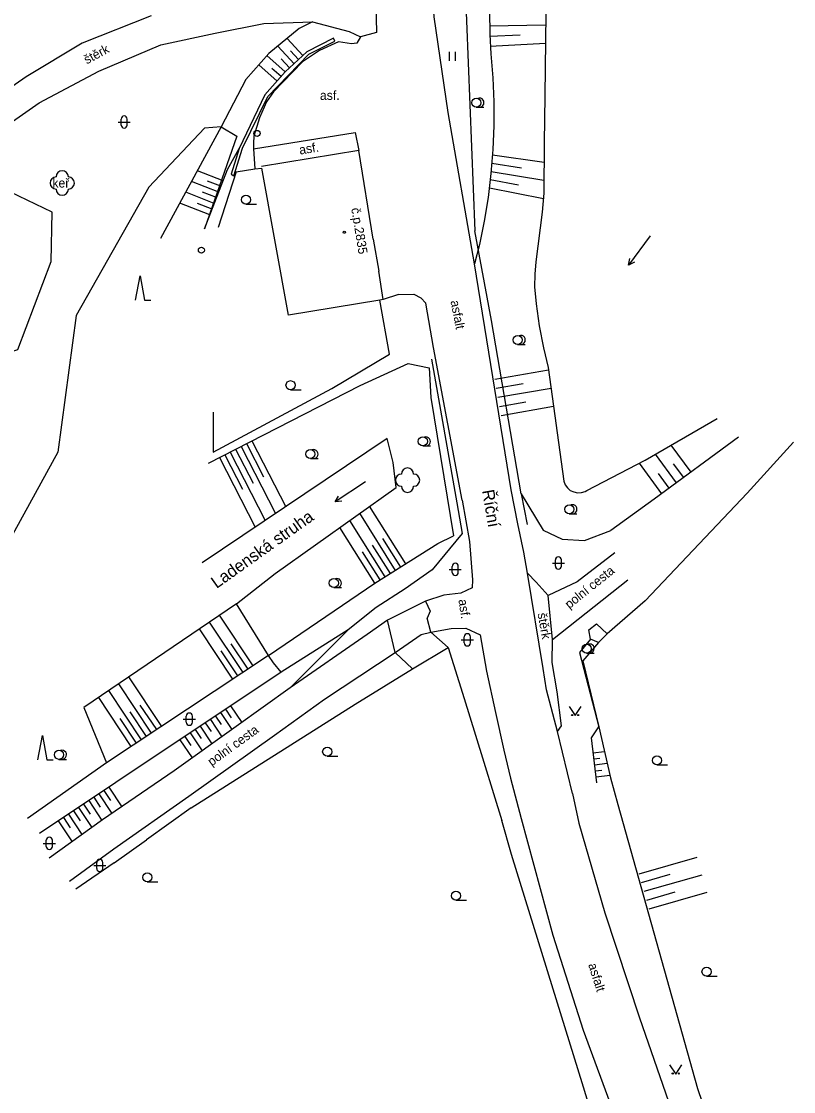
# Model space of a CAD drawing. Extents: x -584400 to -581602, y -1210894 to -1208793.
# Drawn here: x -583059.4 to -582996.1, y -1209395.2 to -1209307.4 of the extents above; entities that cross this region are included whole.
import ezdxf

# ---------------------------------------------------------------- set-up
doc = ezdxf.new("R2010")
doc.units = 0
for name, color, linetype in [('BUDOVY_MĚŘ', 7, 'Continuous'), ('BUDOVY_NEMĚŘ', 7, 'Continuous'), ('NÁZVY_ULIC_TOK_SMĚR', 7, 'Continuous'), ('POMOC_POPIS', 7, 'Continuous'), ('ROZHRANÍ_PLOCH', 7, 'Continuous'), ('VÝŠKOPIS', 7, 'Continuous'), ('ZELEŇ', 7, 'Continuous'), ('ZN_BUDOV', 7, 'Continuous'), ('ZN_DOPLŇKOVÉ', 7, 'Continuous'), ('ZN_KULTUR', 7, 'Continuous'), ('Č_POPIS_ORIENT', 7, 'Continuous')]:
    doc.layers.add(name, color=color, linetype=linetype)

msp = doc.modelspace()

# ---------------------------------------------------------------- linework, layer by layer
at = {"layer": 'BUDOVY_MĚŘ'}
for points in [[(-583030.53, -1209325.27), (-583031.73, -1209318), (-583039.7, -1209319.32)], [(-583029.71, -1209330.22), (-583030.09, -1209327.9)], [(-583029.71, -1209330.22), (-583030, -1209330.27)]]:
    msp.add_lwpolyline(points, dxfattribs=at)
at = {"layer": 'BUDOVY_NEMĚŘ'}
msp.add_lwpolyline([(-583030, -1209330.27), (-583037.49, -1209331.52), (-583039.68, -1209319.45)], dxfattribs=at)
at = {"layer": 'ROZHRANÍ_PLOCH'}
for points in [[(-583024.38, -1209314.88), (-583025.54, -1209307.04), (-583025.97, -1209300.74), (-583026.02, -1209293.23), (-583025.39, -1209285), (-583023.4, -1209274.85), (-583020.65, -1209265.06)], [(-583030.65, -1209293.31), (-583030.43, -1209301.16), (-583030.27, -1209308.32), (-583031.59, -1209308.69)], [(-583048.76, -1209306.95), (-583054.41, -1209309.21), (-583059, -1209311.95), (-583067.75, -1209318.04), (-583077.03, -1209324.86), (-583091.54, -1209334.49), (-583099.69, -1209339.61), (-583098.4, -1209342.8), (-583089.37, -1209336.23), (-583075.72, -1209326.79), (-583066.02, -1209319.73), (-583057.94, -1209314.1), (-583053.04, -1209311.48), (-583047.95, -1209309.34), (-583043.5, -1209308.38), (-583039.51, -1209307.57), (-583035.53, -1209307.45)], [(-583035.53, -1209307.45), (-583032.52, -1209308.24), (-583031.59, -1209308.69)], [(-583031.59, -1209308.69), (-583031.87, -1209309.2), (-583032.31, -1209309.26), (-583033.38, -1209309.08), (-583034.94, -1209309.8), (-583036.35, -1209310.74), (-583038.73, -1209313.19), (-583039.28, -1209314.01), (-583039.88, -1209315.31), (-583040.32, -1209316.82), (-583040.37, -1209317.41), (-583040.35, -1209317.86)], [(-583022.22, -1209327.31), (-583024.38, -1209314.88)], [(-583040.35, -1209317.86), (-583032.01, -1209316.52), (-583031.73, -1209318)], [(-583040.35, -1209317.86), (-583040.24, -1209319.5)], [(-583019.21, -1209345.84), (-583022.22, -1209327.31)], [(-583028.45, -1209329.81), (-583029.71, -1209330.22)], [(-583028.45, -1209329.81), (-583027.2, -1209329.79), (-583026.63, -1209330.08), (-583026.21, -1209330.53)], [(-583025.6, -1209334.16), (-583026.21, -1209330.53)], [(-583023.24, -1209346.69), (-583025.6, -1209334.16)], [(-583014.18, -1209370.76), (-583015.42, -1209365.68), (-583016.33, -1209362.26), (-583016.59, -1209360.5), (-583017.89, -1209352.67), (-583018.19, -1209350.96), (-583018.66, -1209348.63), (-583019.21, -1209345.84)], [(-583023.24, -1209346.69), (-583022.65, -1209350.08), (-583022.39, -1209353.24), (-583022.41, -1209353.88), (-583023.36, -1209354.31), (-583024.75, -1209354.49), (-583026.26, -1209354.99), (-583025.86, -1209355.79), (-583026.12, -1209356.37)], [(-583010.71, -1209351.01), (-583013.81, -1209353.39), (-583016.19, -1209354.51)], [(-583015.42, -1209365.68), (-583015.09, -1209365.2), (-583015.44, -1209362.42), (-583015.87, -1209360), (-583015.83, -1209358.13), (-583016.19, -1209354.51), (-583017.17, -1209353.41), (-583017.89, -1209352.67)], [(-583015.83, -1209358.13), (-583009.66, -1209353.23)], [(-583026.26, -1209354.99), (-583029.37, -1209356.55), (-583031.03, -1209357.71), (-583037.34, -1209362.09), (-583041.77, -1209365.26), (-583046.87, -1209368.89), (-583052.74, -1209372.93), (-583057.12, -1209376.05)], [(-583041.76, -1209355.2), (-583054.27, -1209363.7)], [(-583025.81, -1209357.51), (-583026.12, -1209356.37)], [(-583055.45, -1209377.94), (-583051.81, -1209375.29), (-583045.67, -1209370.97), (-583038.65, -1209365.97), (-583034.54, -1209363.03), (-583028.73, -1209359.18), (-583026.61, -1209357.7), (-583025.81, -1209357.51)], [(-583025.81, -1209357.51), (-583024.13, -1209357.21), (-583022.93, -1209357.18), (-583021.77, -1209357.73), (-583021.25, -1209360.71), (-583020.5, -1209364.12), (-583019.83, -1209367.21), (-583019.28, -1209369.49), (-583018.4, -1209372.8)], [(-583014.18, -1209370.76), (-583013.67, -1209373.19), (-583011.53, -1209380.55), (-583008.69, -1209389.17), (-583006.31, -1209396.03), (-583004.85, -1209400.01), (-583002.36, -1209406.52), (-583001.22, -1209409.38)], [(-583018.4, -1209372.8), (-583015.79, -1209382.38), (-583013.32, -1209390.18), (-583010.75, -1209397.15), (-583007.61, -1209405.53)]]:
    msp.add_lwpolyline(points, dxfattribs=at)
at = {"layer": 'VÝŠKOPIS'}
for points in [[(-583014.89, -1209294.71), (-583015.74, -1209299.14), (-583016.05, -1209301.82), (-583016.37, -1209306.75), (-583016.47, -1209313.52), (-583016.51, -1209317.37), (-583016.55, -1209321.51), (-583016.68, -1209323.06), (-583017.21, -1209327.13)], [(-583020.65, -1209304.48), (-583021.01, -1209306.53), (-583020.98, -1209308.49), (-583020.89, -1209310.07), (-583020.73, -1209312.03), (-583020.65, -1209314), (-583020.65, -1209315.97), (-583020.72, -1209317.93), (-583020.88, -1209319.89), (-583021.12, -1209321.85), (-583021.44, -1209323.79), (-583021.83, -1209325.71), (-583022.22, -1209327.31)], [(-583035.53, -1209307.45), (-583036.6, -1209307.99), (-583039.11, -1209310.04), (-583040.99, -1209312.18), (-583043, -1209316.05)], [(-583016.39, -1209307.72), (-583020.99, -1209307.81)], [(-583036.3, -1209310.2), (-583037.59, -1209308.8)], [(-583018.47, -1209308.55), (-583020.97, -1209308.64)], [(-583016.41, -1209309.22), (-583020.93, -1209309.47)], [(-583037.03, -1209310.88), (-583038.37, -1209309.44)], [(-583036.66, -1209310.54), (-583037.32, -1209309.83)], [(-583038.43, -1209312.31), (-583039.93, -1209310.97)], [(-583037.76, -1209311.56), (-583039.27, -1209310.22)], [(-583037.4, -1209311.22), (-583038.08, -1209310.49)], [(-583038.09, -1209311.94), (-583038.85, -1209311.27)], [(-583043, -1209316.05), (-583047.98, -1209325.21)], [(-583044.39, -1209324.43), (-583042.49, -1209319.55), (-583041.53, -1209317.84)], [(-583016.52, -1209318.98), (-583020.75, -1209318.39)], [(-583042.85, -1209320.48), (-583044.96, -1209319.66)], [(-583016.53, -1209320.47), (-583020.86, -1209319.75)], [(-583018.37, -1209319.44), (-583020.8, -1209319.07)], [(-583043.21, -1209321.41), (-583045.44, -1209320.54)], [(-583043.03, -1209320.94), (-583044.12, -1209320.52)], [(-583018.61, -1209320.85), (-583020.93, -1209320.42)], [(-583043.58, -1209322.34), (-583045.92, -1209321.43)], [(-583043.4, -1209321.87), (-583044.54, -1209321.43)], [(-583016.58, -1209321.97), (-583021.01, -1209321.1)], [(-583043.94, -1209323.27), (-583046.4, -1209322.31)], [(-583043.76, -1209322.81), (-583044.96, -1209322.34)], [(-583017.21, -1209327.13), (-583017.29, -1209328.16), (-583017.3, -1209329.2), (-583017.18, -1209330.59), (-583016.91, -1209332.39), (-583016.57, -1209334.18), (-583016.18, -1209335.82)], [(-583044.05, -1209343.65), (-583031.62, -1209337.27), (-583027.66, -1209335.47), (-583025.96, -1209335.84), (-583025.81, -1209338.27), (-583023.95, -1209349.63)], [(-583016.15, -1209336.03), (-583020.57, -1209336.8)], [(-583016.18, -1209335.82), (-583014.9, -1209345.13)], [(-583018.24, -1209337.16), (-583020.44, -1209337.54)], [(-583015.94, -1209337.52), (-583020.31, -1209338.28)], [(-583018.01, -1209338.64), (-583020.18, -1209339.02)], [(-583015.74, -1209339), (-583020.05, -1209339.76)], [(-583013.01, -1209345.89), (-583008.22, -1209343.4), (-583002.31, -1209340)], [(-583038.57, -1209352.71), (-583028.65, -1209345.64), (-583028.89, -1209343.6), (-583029.39, -1209341.64), (-583044.56, -1209351.82)], [(-583000.57, -1209341.51), (-583007.48, -1209346.6), (-583011.04, -1209349.19)], [(-583041.83, -1209342.51), (-583040.4, -1209345.29)], [(-583041.38, -1209342.28), (-583038.55, -1209347.79)], [(-583040.94, -1209342.05), (-583039.54, -1209344.78)], [(-583040.49, -1209341.82), (-583037.72, -1209347.23)], [(-583006.11, -1209342.18), (-583004.48, -1209344.39)], [(-583043.16, -1209343.19), (-583040.23, -1209348.91)], [(-583042.72, -1209342.97), (-583041.26, -1209345.8)], [(-583042.27, -1209342.74), (-583039.39, -1209348.35)], [(-583007.41, -1209342.93), (-583005.68, -1209345.27)], [(-583008.72, -1209343.66), (-583006.88, -1209346.16)], [(-583005.92, -1209343.7), (-583005.08, -1209344.83)], [(-583014.9, -1209345.13), (-583014.79, -1209345.42), (-583014.61, -1209345.68), (-583014.37, -1209345.89), (-583014.08, -1209346.02), (-583013.78, -1209346.09), (-583013.46, -1209346.07), (-583013.16, -1209345.97), (-583013.01, -1209345.89)], [(-583007.17, -1209344.51), (-583006.28, -1209345.72)], [(-583028.71, -1209352.45), (-583031.64, -1209347.77)], [(-583027.86, -1209351.91), (-583030.83, -1209347.19)], [(-583029.55, -1209352.98), (-583032.46, -1209348.35)], [(-583030.4, -1209353.51), (-583033.27, -1209348.94)], [(-583039.14, -1209359.44), (-583030.4, -1209353.51), (-583025.23, -1209350.26), (-583023.95, -1209349.63)], [(-583029.13, -1209352.71), (-583030.59, -1209350.39)], [(-583028.28, -1209352.18), (-583029.76, -1209349.83)], [(-583029.98, -1209353.24), (-583031.42, -1209350.94)], [(-583041.76, -1209355.2), (-583038.57, -1209352.71)], [(-583040.39, -1209360.27), (-583043.14, -1209356.13)], [(-583028.73, -1209359.18), (-583029.37, -1209356.55)], [(-583042.06, -1209361.38), (-583044.79, -1209357.26)], [(-583041.22, -1209360.82), (-583043.96, -1209356.7)], [(-583032.58, -1209357.33), (-583037.34, -1209362.09)], [(-583025.81, -1209357.51), (-583024.39, -1209358.79)], [(-583012.7, -1209358.09), (-583012.84, -1209357.32), (-583012.23, -1209356.85), (-583011.34, -1209357.65)], [(-583041.64, -1209361.1), (-583043.01, -1209359.04)], [(-583040.81, -1209360.55), (-583042.18, -1209358.48)], [(-583028.73, -1209359.18), (-583027.32, -1209360.53)], [(-583039.14, -1209359.44), (-583052.41, -1209368.25)], [(-583038.1, -1209360.8), (-583051.65, -1209369.86), (-583057.92, -1209374.03)], [(-583048.72, -1209365.8), (-583051.41, -1209361.75)], [(-583047.89, -1209365.25), (-583050.58, -1209361.19)], [(-583049.55, -1209366.35), (-583052.23, -1209362.32)], [(-583050.39, -1209366.91), (-583053.06, -1209362.88)], [(-583048.3, -1209365.52), (-583049.65, -1209363.5)], [(-583042.24, -1209363.57), (-583041.32, -1209364.94)], [(-583049.14, -1209366.08), (-583050.48, -1209364.06)], [(-583043.49, -1209364.4), (-583043.02, -1209365.11)], [(-583043.07, -1209364.12), (-583042.14, -1209365.52)], [(-583042.66, -1209363.85), (-583042.19, -1209364.54)], [(-583049.97, -1209366.63), (-583051.31, -1209364.61)], [(-583044.73, -1209365.24), (-583043.77, -1209366.68)], [(-583044.32, -1209364.96), (-583043.84, -1209365.67)], [(-583043.9, -1209364.68), (-583042.95, -1209366.1)], [(-583012.2, -1209369.89), (-583012.64, -1209366.18), (-583012.04, -1209365.3)], [(-583045.98, -1209366.07), (-583045.49, -1209366.81)], [(-583045.56, -1209365.79), (-583044.58, -1209367.26)], [(-583045.15, -1209365.51), (-583044.66, -1209366.24)], [(-583046.4, -1209366.35), (-583045.4, -1209367.84)], [(-583012.49, -1209367.41), (-583011.58, -1209367.3)], [(-583012.44, -1209367.9), (-583011.95, -1209367.85)], [(-583012.38, -1209368.4), (-583011.35, -1209368.28)], [(-583012.32, -1209368.9), (-583011.78, -1209368.83)], [(-583012.26, -1209369.39), (-583011.12, -1209369.26)], [(-583052.63, -1209370.51), (-583052.1, -1209371.32)], [(-583052.22, -1209370.24), (-583051.15, -1209371.84)], [(-583053.88, -1209371.34), (-583052.8, -1209372.97)], [(-583053.47, -1209371.07), (-583052.93, -1209371.88)], [(-583053.05, -1209370.79), (-583051.98, -1209372.4)], [(-583055.13, -1209372.17), (-583054.58, -1209373.01)], [(-583054.71, -1209371.9), (-583053.61, -1209373.55)], [(-583054.3, -1209371.62), (-583053.75, -1209372.44)], [(-583056.38, -1209373.01), (-583055.24, -1209374.71)], [(-583055.96, -1209372.73), (-583055.4, -1209373.58)], [(-583055.55, -1209372.45), (-583054.43, -1209374.13)], [(-583004, -1209376), (-583008.76, -1209377.37)], [(-583006.19, -1209377.41), (-583008.55, -1209378.09)], [(-583003.58, -1209377.45), (-583008.34, -1209378.81)], [(-583005.78, -1209378.86), (-583008.13, -1209379.53)], [(-583003.17, -1209378.89), (-583007.92, -1209380.25)]]:
    msp.add_lwpolyline(points, dxfattribs=at)
at = {"layer": 'ZELEŇ'}
for points in [[(-583023.02, -1209303.89), (-583022.2, -1209324.58)], [(-583043, -1209316.05), (-583044.38, -1209316.16), (-583048.94, -1209321.01), (-583054.92, -1209331.55), (-583056.41, -1209342.75), (-583061.85, -1209352.63), (-583069.22, -1209360.34), (-583096.19, -1209376.59), (-583130.78, -1209402.41), (-583140.19, -1209404.77), (-583148.02, -1209386.1), (-583155.04, -1209381.85)], [(-583043, -1209316.05), (-583041.72, -1209316.84), (-583044.39, -1209324.43)], [(-583060.3, -1209321.43), (-583063.49, -1209323.85), (-583066.72, -1209328.07), (-583063.31, -1209335.53), (-583059.69, -1209334.33), (-583056.96, -1209327.11), (-583056.89, -1209323.07), (-583060.3, -1209321.43)], [(-583018.39, -1209346.18), (-583016.6, -1209349.16), (-583015.03, -1209349.89), (-583013.21, -1209350.01), (-583011.04, -1209349.19)], [(-583023.25, -1209349.42), (-583025.71, -1209352.42), (-583027.91, -1209353.96), (-583030.29, -1209355.49), (-583032.58, -1209357.33), (-583038.1, -1209360.8), (-583038.73, -1209360.05), (-583039.14, -1209359.44), (-583041.76, -1209355.2)], [(-583054.27, -1209363.7), (-583052.41, -1209368.25), (-583058.9, -1209372.81)]]:
    msp.add_lwpolyline(points, dxfattribs=at)
for centre in [(-583056.05, -1209320.67), (-583027.72, -1209345.05)]:
    msp.add_circle(centre, 0.0005, dxfattribs=at)
for centre, start, end in [((-583056.05, -1209320.17), 0, 179.99999), ((-583056.55, -1209320.67), 89.99999, 269.99999), ((-583055.55, -1209320.67), 270, 89.99999), ((-583056.05, -1209321.17), 179.99999, 359.99999), ((-583027.72, -1209344.55), 0, 179.99999), ((-583028.22, -1209345.05), 89.99999, 269.99999), ((-583027.22, -1209345.05), 270, 89.99999), ((-583027.72, -1209345.55), 179.99999, 359.99999)]:
    msp.add_arc(centre, 0.5, start, end, dxfattribs=at)
at = {"layer": 'ZN_BUDOV'}
msp.add_circle((-583032.91, -1209324.71), 0.0875, dxfattribs=at)
at = {"layer": 'ZN_DOPLŇKOVÉ'}
for points in [[(-583041.53, -1209317.84), (-583042.19, -1209319.95), (-583041.96, -1209320.07), (-583041.27, -1209317.82), (-583039.19, -1209313.57), (-583035.83, -1209310.09), (-583033.68, -1209309.03), (-583033.79, -1209308.79), (-583035.99, -1209309.92), (-583037.76, -1209311.56), (-583039.43, -1209313.44), (-583041.53, -1209317.84)], [(-583041.79, -1209319.75), (-583043.25, -1209324.33)], [(-583041.79, -1209319.75), (-583040.24, -1209319.5)], [(-583040.24, -1209319.5), (-583039.68, -1209319.45)], [(-583018.39, -1209346.18), (-583020.83, -1209331.94), (-583022.2, -1209324.58)], [(-583030.53, -1209325.27), (-583030.09, -1209327.9)], [(-583029.19, -1209334.71), (-583030, -1209330.27)], [(-583033.93, -1209337.54), (-583029.19, -1209334.71)], [(-583025.75, -1209335.12), (-583023.68, -1209346.91)], [(-583043.68, -1209342.76), (-583033.93, -1209337.54)], [(-583043.68, -1209339.47), (-583043.68, -1209342.76)], [(-582999.86, -1209346.13), (-582996.05, -1209341.92)], [(-583023.68, -1209346.91), (-583023.25, -1209349.42)], [(-583018.39, -1209346.18), (-583017.92, -1209348.69)], [(-582999.86, -1209346.13), (-583008.22, -1209354.95)], [(-583008.22, -1209354.95), (-583011.34, -1209357.65)], [(-583012.06, -1209358.38), (-583012.7, -1209358.09), (-583013.62, -1209359.2), (-583012.04, -1209365.3)], [(-583012.06, -1209358.38), (-583013.34, -1209359.86), (-583012.04, -1209365.3), (-583011.07, -1209369.46), (-583010.46, -1209371.65)], [(-583012.06, -1209358.38), (-583011.34, -1209357.65)], [(-583045.47, -1209371.92), (-583032.01, -1209363.43), (-583027.32, -1209360.53), (-583024.39, -1209358.79), (-583023.07, -1209362.97)], [(-583023.07, -1209362.97), (-583022.14, -1209365.97)], [(-583022.14, -1209365.97), (-583019.98, -1209372.98)], [(-583045.47, -1209371.92), (-583049.14, -1209374.56)], [(-583010.46, -1209371.65), (-583003.94, -1209394.97)], [(-583013.29, -1209394.86), (-583019.18, -1209375.75), (-583019.98, -1209372.98)], [(-583051.79, -1209376.45), (-583049.14, -1209374.56)], [(-583051.79, -1209376.45), (-583054.93, -1209378.61)], [(-583012.91, -1209396.1), (-583013.29, -1209394.86)], [(-583003.94, -1209394.97), (-583002.84, -1209398.16)]]:
    msp.add_lwpolyline(points, dxfattribs=at)
for centre, radius in [((-583040.07, -1209316.6), 0.25), ((-583040.07, -1209316.6), 0.0005), ((-583044.63, -1209326.18), 0.25), ((-583044.63, -1209326.18), 0.0005)]:
    msp.add_circle(centre, radius, dxfattribs=at)
at = {"layer": 'ZN_KULTUR'}
for p, q in [((-583024.28, -1209310.645), (-583024.28, -1209309.895)), ((-583023.78, -1209310.645), (-583023.78, -1209309.895)), ((-583022.08, -1209314.455), (-583021.455, -1209314.455)), ((-583051.47, -1209315.67), (-583050.47, -1209315.67)), ((-583051.22, -1209315.92), (-583051.22, -1209315.42)), ((-583050.72, -1209315.92), (-583050.72, -1209315.42)), ((-583040.98, -1209322.415), (-583040.105, -1209322.415)), ((-583007.813, -1209325), (-583009.587, -1209327.42)), ((-583018.69, -1209333.925), (-583018.065, -1209333.925)), ((-583037.32, -1209337.635), (-583036.445, -1209337.635)), ((-583026.47, -1209342.245), (-583025.845, -1209342.245)), ((-583035.69, -1209343.285), (-583035.065, -1209343.285)), ((-583031.169, -1209345.183), (-583033.671, -1209346.837)), ((-583014.45, -1209347.815), (-583013.825, -1209347.815)), ((-583024.06, -1209352.62), (-583024.06, -1209352.12)), ((-583023.56, -1209352.62), (-583023.56, -1209352.12)), ((-583015.84, -1209351.85), (-583014.84, -1209351.85)), ((-583015.59, -1209352.1), (-583015.59, -1209351.6)), ((-583015.09, -1209352.1), (-583015.09, -1209351.6)), ((-583024.31, -1209352.37), (-583023.31, -1209352.37)), ((-583033.77, -1209353.865), (-583033.145, -1209353.865)), ((-583023.32, -1209358.15), (-583022.32, -1209358.15)), ((-583023.07, -1209358.4), (-583023.07, -1209357.9)), ((-583022.57, -1209358.4), (-583022.57, -1209357.9)), ((-583013.03, -1209359.245), (-583012.405, -1209359.245)), ((-583045.87, -1209364.91), (-583045.87, -1209364.41)), ((-583045.37, -1209364.91), (-583045.37, -1209364.41)), ((-583046.12, -1209364.66), (-583045.12, -1209364.66)), ((-583056.32, -1209367.955), (-583055.695, -1209367.955)), ((-583034.31, -1209367.705), (-583033.435, -1209367.705)), ((-583007.26, -1209368.415), (-583006.385, -1209368.415)), ((-583057.61, -1209374.85), (-583056.61, -1209374.85)), ((-583057.36, -1209375.1), (-583057.36, -1209374.6)), ((-583056.86, -1209375.1), (-583056.86, -1209374.6)), ((-583053.47, -1209376.66), (-583052.47, -1209376.66)), ((-583053.22, -1209376.91), (-583053.22, -1209376.41)), ((-583052.72, -1209376.91), (-583052.72, -1209376.41)), ((-583049.07, -1209378.015), (-583048.195, -1209378.015)), ((-583023.75, -1209379.515), (-583022.875, -1209379.515)), ((-583003.19, -1209385.755), (-583002.315, -1209385.755))]:
    msp.add_line(p, q, dxfattribs=at)
for points in [[(-583009.089, -1209327.164), (-583009.587, -1209327.42), (-583009.493, -1209326.869)], [(-583050.045, -1209330.29), (-583049.67, -1209328.29), (-583049.295, -1209330.29), (-583048.795, -1209330.29)], [(-583033.117, -1209346.77), (-583033.671, -1209346.837), (-583033.392, -1209346.353)], [(-583014.47, -1209363.62), (-583013.97, -1209364.37), (-583013.47, -1209363.62)], [(-583058.055, -1209367.99), (-583057.68, -1209365.99), (-583057.305, -1209367.99), (-583056.805, -1209367.99)], [(-583006.22, -1209393.03), (-583005.72, -1209393.78), (-583005.22, -1209393.03)]]:
    msp.add_lwpolyline(points, dxfattribs=at)
for centre, radius in [((-583022.08, -1209314.08), 0.375), ((-583040.98, -1209322.04), 0.375), ((-583018.69, -1209333.55), 0.375), ((-583037.32, -1209337.26), 0.375), ((-583026.47, -1209341.87), 0.375), ((-583035.69, -1209342.91), 0.375), ((-583014.45, -1209347.44), 0.375), ((-583033.77, -1209353.49), 0.375), ((-583013.03, -1209358.87), 0.375), ((-583014.22, -1209364.32), 0.05), ((-583013.72, -1209364.32), 0.05), ((-583034.31, -1209367.33), 0.375), ((-583056.32, -1209367.58), 0.375), ((-583007.26, -1209368.04), 0.375), ((-583049.07, -1209377.64), 0.375), ((-583023.75, -1209379.14), 0.375), ((-583003.19, -1209385.38), 0.375), ((-583005.97, -1209393.73), 0.05), ((-583005.47, -1209393.73), 0.05)]:
    msp.add_circle(centre, radius, dxfattribs=at)
for centre, radius, start, end in [((-583021.83, -1209314.08), 0.375, 249.49437, 109.04743), ((-583050.97, -1209315.42), 0.25, 0, 179.99999), ((-583050.97, -1209315.92), 0.25, 179.99999, 359.99999), ((-583018.44, -1209333.55), 0.375, 249.49437, 109.04743), ((-583026.22, -1209341.87), 0.375, 249.49437, 109.04743), ((-583035.44, -1209342.91), 0.375, 249.49437, 109.04743), ((-583014.2, -1209347.44), 0.375, 249.49437, 109.04743), ((-583015.34, -1209351.6), 0.25, 0, 179.99999), ((-583023.81, -1209352.12), 0.25, 0, 179.99999), ((-583015.34, -1209352.1), 0.25, 179.99999, 359.99999), ((-583033.52, -1209353.49), 0.375, 249.49437, 109.04743), ((-583023.81, -1209352.62), 0.25, 179.99999, 359.99999), ((-583022.82, -1209357.9), 0.25, 0, 179.99999), ((-583022.82, -1209358.4), 0.25, 179.99999, 359.99999), ((-583012.78, -1209358.87), 0.375, 249.49437, 109.04743), ((-583045.62, -1209364.41), 0.25, 0, 179.99999), ((-583045.62, -1209364.91), 0.25, 179.99999, 359.99999), ((-583056.07, -1209367.58), 0.375, 249.49437, 109.04743), ((-583057.11, -1209374.6), 0.25, 0, 179.99999), ((-583057.11, -1209375.1), 0.25, 179.99999, 359.99999), ((-583052.97, -1209376.41), 0.25, 0, 179.99999), ((-583052.97, -1209376.91), 0.25, 179.99999, 359.99999)]:
    msp.add_arc(centre, radius, start, end, dxfattribs=at)

# ---------------------------------------------------------------- texts
at = {"layer": 'NÁZVY_ULIC_TOK_SMĚR'}
for s, rotation, p in [('Říční', 279.90856, (-583021.62, -1209345.91)), ('Ladenská struha', 35.33637, (-583043.39, -1209353.98))]:
    msp.add_text(s, height=1, rotation=rotation, dxfattribs=at).set_placement(p)
at = {"layer": 'POMOC_POPIS'}
for s, rotation, p in [('štěrk', 28.13314, (-583054.03, -1209310.94)), ('asf.', 9.40401, (-583036.55, -1209318.34)), ('asfalt', 280.90705, (-583024.2, -1209330.36)), ('polní cesta', 38.7854, (-583014.45, -1209355.64)), ('asf.', 278.45502, (-583023.55, -1209354.87)), ('štěrk', 280.01295, (-583017.06, -1209356)), ('polní cesta', 35.97688, (-583043.79, -1209368.54)), ('asfalt', 287.57124, (-583012.91, -1209384.8))]:
    msp.add_text(s, height=0.75, rotation=rotation, dxfattribs=at).set_placement(p)
msp.add_text('asf.', height=0.75, dxfattribs=at).set_placement((-583034.91, -1209313.85))
at = {"layer": 'ZELEŇ'}
msp.add_text('keř', height=0.75, dxfattribs=at).set_placement((-583056.86, -1209321.04))
at = {"layer": 'Č_POPIS_ORIENT'}
msp.add_text('č.p.2835', height=0.75, rotation=279.38001, dxfattribs=at).set_placement((-583032.35, -1209322.76))

doc.saveas('drawing.dxf')
